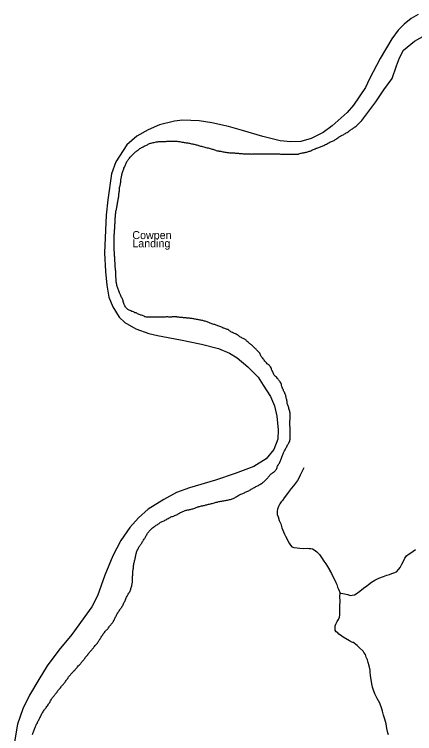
# Model space of a CAD drawing. Extents: x 1945482 to 2853149, y 66427 to 1015778.
# Drawn here: x 2303586 to 2310973, y 217061 to 230327 of the extents above; entities that cross this region are included whole.
import ezdxf

# ---------------------------------------------------------------- set-up
doc = ezdxf.new("R2010")
doc.units = 0
for name, color, linetype in [('Old_Level_21', 7, 'Continuous'), ('Old_Level_35', 7, 'Continuous'), ('Old_Level_52', 7, 'Continuous'), ('Old_Level_60', 7, 'Continuous')]:
    doc.layers.add(name, color=color, linetype=linetype)

msp = doc.modelspace()

# ---------------------------------------------------------------- linework, layer by layer
at = {"layer": 'Old_Level_35'}
for points in [[(2308930, 221960), (2308883, 221878), (2308861, 221825), (2308835, 221772), (2308809, 221729), (2308777, 221678), (2308739, 221628), (2308697, 221579), (2308640, 221510), (2308606, 221465), (2308566, 221409), (2308532, 221360), (2308511, 221335), (2308484, 221296), (2308460, 221251), (2308444, 221199), (2308439, 221164), (2308438, 221104), (2308452, 221059), (2308474, 220994), (2308501, 220929), (2308522, 220859), (2308574, 220738), (2308592, 220702), (2308655, 220571), (2308681, 220534), (2308704, 220505), (2308742, 220492), (2308804, 220485), (2308857, 220479), (2308913, 220475), (2308991, 220478), (2309025, 220475), (2309055, 220475), (2309089, 220466), (2309116, 220451), (2309171, 220415), (2309217, 220367), (2309252, 220310), (2309300, 220244), (2309334, 220193), (2309368, 220145), (2309399, 220082), (2309401, 220078), (2309437, 220016), (2309459, 219972), (2309485, 219913), (2309516, 219847), (2309535, 219811), (2309549, 219764), (2309569, 219723), (2309598, 219648)], [(2309598, 219648), (2309650, 219644), (2309741, 219627), (2309782, 219611), (2309823, 219613), (2309863, 219622), (2309895, 219638), (2309959, 219688), (2310032, 219745), (2310089, 219789), (2310122, 219813), (2310176, 219851), (2310239, 219891), (2310315, 219926), (2310396, 219960), (2310461, 219984), (2310508, 219998), (2310552, 220014), (2310605, 220032), (2310637, 220047), (2310679, 220093), (2310704, 220122), (2310739, 220189), (2310765, 220242), (2310791, 220299), (2310821, 220342), (2310852, 220366), (2310903, 220398), (2310944, 220423), (2310989, 220455)], [(2310488, 217040), (2310476, 217076), (2310459, 217155), (2310446, 217241), (2310422, 217326), (2310401, 217403), (2310382, 217476), (2310369, 217518), (2310333, 217622), (2310283, 217708), (2310238, 217797), (2310213, 217862), (2310197, 217919), (2310186, 217979), (2310160, 218130), (2310154, 218191), (2310152, 218229), (2310135, 218313), (2310115, 218370), (2310101, 218421), (2310081, 218473), (2310065, 218518), (2310037, 218557), (2310022, 218580), (2309956, 218642), (2309910, 218684), (2309830, 218745), (2309826, 218743), (2309773, 218774), (2309656, 218840), (2309605, 218874), (2309576, 218893), (2309553, 218918), (2309526, 218935), (2309507, 218968), (2309504, 219048), (2309518, 219082), (2309545, 219126), (2309569, 219164), (2309587, 219211), (2309592, 219247), (2309593, 219321), (2309593, 219412), (2309596, 219502), (2309592, 219590), (2309598, 219648)]]:
    msp.add_lwpolyline(points, dxfattribs=at)
at = {"layer": 'Old_Level_52'}
msp.add_lwpolyline([(2311041, 230327), (2310910, 230249), (2310777, 230148), (2310670, 230033), (2310554, 229875), (2310336, 229511), (2310143, 229139), (2310065, 228980), (2309845, 228651), (2309729, 228516), (2309451, 228274), (2309282, 228148), (2309061, 228036), (2308875, 227983), (2308686, 227974), (2308492, 227992), (2308171, 228072), (2307797, 228186), (2307537, 228258), (2307232, 228325), (2306995, 228361), (2306690, 228374), (2306539, 228359), (2306266, 228287), (2306053, 228199), (2305845, 228081), (2305659, 227920), (2305456, 227604), (2305381, 227384), (2305314, 226908), (2305283, 226623), (2305247, 225931), (2305247, 225931), (2305265, 225583), (2305293, 225333), (2305328, 225110), (2305406, 224932), (2305520, 224739), (2305626, 224645), (2305825, 224528), (2306065, 224443), (2306226, 224401), (2306654, 224325), (2307038, 224244), (2307353, 224161), (2307554, 224075), (2307698, 223989), (2307895, 223827), (2308085, 223633), (2308179, 223490), (2308310, 223279), (2308388, 223107), (2308432, 222916), (2308454, 222664), (2308446, 222492), (2308372, 222302), (2308230, 222131), (2308004, 221990), (2307659, 221856), (2307298, 221737), (2306817, 221594), (2306579, 221508), (2306342, 221379), (2306056, 221201), (2305876, 221040), (2305718, 220861), (2305551, 220621), (2305403, 220340), (2305258, 219982), (2305119, 219603), (2305015, 219398), (2304645, 218886), (2304404, 218602), (2304191, 218309), (2304038, 218060), (2303863, 217767), (2303743, 217519), (2303641, 217232), (2303586, 216908)], dxfattribs=at)
at = {"layer": 'Old_Level_60'}
for points in [[(2310000, 228370), (2310254, 228715), (2310403, 228933), (2310561, 229143), (2310636, 229379), (2310692, 229527), (2310766, 229667), (2310971, 229833), (2311265, 230000)], [(2308766, 227748), (2308782, 227748), (2308799, 227748), (2308815, 227749), (2308828, 227751), (2308838, 227757), (2308854, 227760), (2308871, 227764), (2308888, 227767), (2308904, 227770), (2308920, 227775), (2308935, 227778), (2308951, 227782), (2308966, 227787), (2308982, 227788), (2308997, 227794), (2309013, 227797), (2309029, 227801), (2309043, 227806), (2309060, 227812), (2309076, 227820), (2309090, 227826), (2309107, 227833), (2309125, 227841), (2309140, 227848), (2309154, 227856), (2309171, 227862), (2309187, 227867), (2309203, 227872), (2309219, 227878), (2309233, 227884), (2309248, 227890), (2309264, 227897), (2309280, 227903), (2309296, 227910), (2309313, 227918), (2309329, 227926), (2309345, 227935), (2309362, 227944), (2309378, 227952), (2309392, 227960), (2309409, 227967), (2309423, 227973), (2309438, 227979), (2309455, 227987), (2309471, 227994), (2309485, 228002), (2309498, 228011), (2309512, 228018), (2309525, 228028), (2309539, 228037), (2309555, 228049), (2309568, 228058), (2309581, 228066), (2309594, 228076), (2309609, 228086), (2309623, 228093), (2309638, 228099), (2309651, 228107), (2309665, 228112), (2309681, 228121), (2309697, 228130), (2309711, 228139), (2309727, 228148), (2309745, 228159), (2309759, 228170), (2309772, 228179), (2309785, 228189), (2309797, 228198), (2309809, 228208), (2309824, 228218), (2309837, 228226), (2309850, 228235), (2309865, 228245), (2309878, 228254), (2309892, 228265), (2309906, 228276), (2309918, 228288), (2309929, 228299), (2309940, 228310), (2309952, 228320), (2309961, 228332), (2309973, 228343), (2309985, 228355), (2309996, 228366), (2310000, 228370)], [(2305449, 226575), (2305450, 226593), (2305452, 226609), (2305454, 226627), (2305455, 226644), (2305456, 226660), (2305458, 226677), (2305460, 226695), (2305464, 226712), (2305469, 226728), (2305473, 226744), (2305476, 226759), (2305479, 226777), (2305481, 226796), (2305484, 226813), (2305487, 226830), (2305490, 226850), (2305493, 226867), (2305496, 226885), (2305499, 226900), (2305502, 226916), (2305505, 226934), (2305508, 226950), (2305511, 226965), (2305514, 226981), (2305516, 226999), (2305517, 227017), (2305519, 227034), (2305523, 227052), (2305525, 227070), (2305526, 227086), (2305527, 227102), (2305527, 227118), (2305529, 227134), (2305533, 227149), (2305536, 227164), (2305539, 227181), (2305542, 227198), (2305545, 227213), (2305548, 227229), (2305550, 227247), (2305551, 227263), (2305554, 227279), (2305556, 227294), (2305559, 227309), (2305562, 227324), (2305564, 227340), (2305567, 227355), (2305570, 227370), (2305574, 227386), (2305578, 227400), (2305583, 227415), (2305587, 227430), (2305593, 227446), (2305598, 227461), (2305604, 227476), (2305609, 227491), (2305616, 227507), (2305622, 227523), (2305628, 227536), (2305636, 227550), (2305644, 227564), (2305651, 227581), (2305657, 227596), (2305664, 227612), (2305671, 227625), (2305682, 227639), (2305691, 227652), (2305701, 227663), (2305711, 227677), (2305722, 227690), (2305735, 227704), (2305747, 227717), (2305759, 227728), (2305772, 227742), (2305784, 227755), (2305796, 227766), (2305810, 227778), (2305822, 227789), (2305834, 227800), (2305849, 227812), (2305863, 227822), (2305877, 227831), (2305889, 227841), (2305904, 227850), (2305922, 227862), (2305935, 227870), (2305948, 227878), (2305961, 227885), (2305979, 227893), (2305995, 227900), (2306011, 227908), (2306027, 227915), (2306042, 227921), (2306055, 227930), (2306069, 227938), (2306082, 227946), (2306097, 227950), (2306112, 227954)], [(2306112, 227954), (2306130, 227958), (2306147, 227962), (2306165, 227966), (2306184, 227970), (2306200, 227973), (2306214, 227976), (2306232, 227978), (2306247, 227980), (2306263, 227981), (2306278, 227982), (2306297, 227983), (2306316, 227984), (2306334, 227984), (2306351, 227985), (2306367, 227985), (2306385, 227985), (2306401, 227986), (2306417, 227987), (2306436, 227989), (2306455, 227989), (2306471, 227989), (2306488, 227990), (2306507, 227990), (2306526, 227990), (2306544, 227989), (2306562, 227988), (2306577, 227987), (2306593, 227986), (2306610, 227983), (2306626, 227979), (2306641, 227979), (2306657, 227974), (2306674, 227971), (2306690, 227970), (2306706, 227967), (2306722, 227965), (2306738, 227962), (2306755, 227959), (2306770, 227957), (2306788, 227955), (2306805, 227953), (2306821, 227949), (2306837, 227944), (2306854, 227941), (2306873, 227938), (2306891, 227935), (2306906, 227931), (2306921, 227927), (2306939, 227922), (2306955, 227918), (2306971, 227914), (2306987, 227909), (2307002, 227904), (2307022, 227898), (2307040, 227893), (2307059, 227888), (2307080, 227883), (2307101, 227878), (2307122, 227873), (2307142, 227868), (2307161, 227863), (2307180, 227859), (2307199, 227854), (2307217, 227848), (2307234, 227843), (2307249, 227839), (2307266, 227834), (2307282, 227828), (2307298, 227822), (2307313, 227815), (2307328, 227812), (2307344, 227810), (2307358, 227808), (2307367, 227803), (2307383, 227802), (2307399, 227801), (2307415, 227796), (2307433, 227793), (2307451, 227790), (2307469, 227786), (2307488, 227783), (2307505, 227781), (2307523, 227779), (2307540, 227777), (2307555, 227776), (2307571, 227775), (2307586, 227776), (2307602, 227776), (2307617, 227774), (2307633, 227773), (2307651, 227771), (2307669, 227769), (2307687, 227767), (2307706, 227766), (2307721, 227765), (2307736, 227763), (2307752, 227762), (2307770, 227760)], [(2307770, 227760), (2307790, 227758), (2307808, 227757), (2307828, 227756), (2307844, 227755), (2307859, 227755), (2307878, 227755), (2307895, 227754), (2307911, 227753), (2307930, 227752), (2307949, 227752), (2307964, 227751), (2307981, 227752), (2308000, 227752), (2308015, 227753), (2308039, 227753), (2308054, 227753), (2308073, 227754), (2308092, 227754), (2308108, 227753), (2308125, 227753), (2308140, 227753), (2308162, 227753), (2308183, 227753), (2308203, 227753), (2308222, 227753), (2308241, 227752), (2308260, 227752), (2308278, 227752), (2308297, 227753), (2308317, 227753), (2308341, 227754), (2308356, 227754), (2308375, 227754), (2308395, 227754), (2308411, 227754), (2308429, 227754), (2308444, 227753), (2308463, 227753), (2308482, 227752), (2308499, 227751), (2308515, 227751), (2308533, 227751), (2308548, 227751), (2308564, 227751), (2308580, 227749), (2308595, 227749), (2308611, 227749), (2308628, 227749), (2308645, 227749), (2308663, 227749), (2308683, 227747), (2308700, 227746), (2308717, 227747), (2308733, 227747), (2308748, 227747), (2308766, 227748)], [(2305449, 225659), (2305448, 225677), (2305447, 225696), (2305446, 225713), (2305445, 225729), (2305444, 225749), (2305443, 225764), (2305443, 225781), (2305442, 225797), (2305441, 225816), (2305439, 225834), (2305438, 225850), (2305437, 225867), (2305437, 225882), (2305437, 225898), (2305436, 225915), (2305435, 225930), (2305432, 225945), (2305429, 225962), (2305428, 225977), (2305428, 225994), (2305428, 226010), (2305427, 226028), (2305427, 226044), (2305427, 226060), (2305430, 226077), (2305431, 226092), (2305431, 226108), (2305430, 226123), (2305430, 226139), (2305430, 226155), (2305429, 226171), (2305430, 226187), (2305430, 226203), (2305430, 226219), (2305429, 226235), (2305430, 226251), (2305431, 226267), (2305432, 226283), (2305432, 226301), (2305433, 226318), (2305435, 226337), (2305437, 226354), (2305439, 226372), (2305440, 226391), (2305441, 226407), (2305441, 226424), (2305442, 226439), (2305443, 226456), (2305445, 226474), (2305446, 226492), (2305446, 226509), (2305447, 226525), (2305447, 226542), (2305448, 226560), (2305449, 226575)], [(2306455, 224744), (2306437, 224744), (2306421, 224745), (2306404, 224745), (2306387, 224745), (2306368, 224744), (2306352, 224744), (2306334, 224743), (2306317, 224743), (2306301, 224743), (2306286, 224744), (2306270, 224744), (2306254, 224744), (2306236, 224744), (2306220, 224743), (2306205, 224743), (2306190, 224743), (2306173, 224742), (2306158, 224742), (2306142, 224742), (2306126, 224741), (2306107, 224741), (2306089, 224741), (2306073, 224740), (2306055, 224742), (2306040, 224743), (2306023, 224744), (2306008, 224745), (2305993, 224750), (2305979, 224758), (2305964, 224766), (2305950, 224771), (2305934, 224776), (2305920, 224781), (2305905, 224786), (2305891, 224793), (2305876, 224799), (2305861, 224806), (2305847, 224813), (2305832, 224819), (2305824, 224822), (2305812, 224824), (2305798, 224832), (2305784, 224839), (2305769, 224844), (2305753, 224849), (2305738, 224858), (2305724, 224863), (2305707, 224871), (2305693, 224877), (2305679, 224885), (2305667, 224896), (2305656, 224907), (2305644, 224920), (2305636, 224935), (2305627, 224948), (2305618, 224963), (2305612, 224978), (2305607, 224994), (2305602, 225012), (2305597, 225028), (2305591, 225043), (2305586, 225059), (2305579, 225076), (2305573, 225090), (2305565, 225105), (2305559, 225120), (2305553, 225135), (2305546, 225151), (2305538, 225164), (2305530, 225178), (2305524, 225193), (2305518, 225209), (2305511, 225228), (2305505, 225243), (2305499, 225260), (2305495, 225276), (2305490, 225294), (2305485, 225309), (2305479, 225328), (2305475, 225344), (2305471, 225361), (2305469, 225377), (2305467, 225392), (2305466, 225408), (2305465, 225426), (2305463, 225443), (2305462, 225459), (2305461, 225476), (2305460, 225496), (2305459, 225513), (2305459, 225533), (2305458, 225552), (2305457, 225571), (2305456, 225592), (2305454, 225608), (2305453, 225627), (2305451, 225643), (2305449, 225659)], [(2307924, 224258), (2307911, 224269), (2307898, 224281), (2307885, 224292), (2307872, 224303), (2307861, 224316), (2307850, 224326), (2307837, 224335), (2307823, 224340), (2307809, 224349), (2307793, 224357), (2307778, 224365), (2307762, 224373), (2307749, 224381), (2307736, 224391), (2307723, 224401), (2307710, 224411), (2307695, 224419), (2307681, 224426), (2307665, 224434), (2307648, 224443), (2307631, 224449), (2307613, 224456), (2307596, 224464), (2307581, 224473), (2307567, 224481), (2307555, 224492), (2307542, 224503), (2307530, 224512), (2307515, 224517), (2307499, 224520), (2307484, 224525), (2307469, 224530), (2307454, 224536), (2307440, 224542), (2307426, 224549), (2307409, 224556), (2307394, 224564), (2307377, 224571), (2307361, 224577), (2307344, 224583), (2307329, 224588), (2307313, 224593), (2307298, 224599), (2307283, 224604), (2307268, 224608), (2307250, 224613), (2307233, 224619), (2307218, 224625), (2307202, 224632), (2307188, 224637), (2307173, 224644), (2307158, 224649), (2307143, 224653), (2307126, 224659), (2307108, 224666), (2307094, 224671), (2307079, 224675), (2307063, 224678), (2307048, 224682), (2307030, 224684), (2307015, 224688), (2306999, 224692), (2306985, 224695), (2306965, 224698), (2306949, 224700), (2306931, 224705), (2306915, 224707), (2306900, 224711), (2306885, 224714), (2306868, 224715), (2306852, 224718), (2306836, 224720), (2306819, 224721), (2306801, 224721), (2306785, 224723), (2306770, 224725), (2306755, 224729), (2306739, 224732), (2306724, 224732), (2306707, 224732), (2306691, 224734), (2306676, 224736), (2306659, 224737), (2306642, 224737), (2306624, 224740), (2306608, 224741), (2306592, 224743), (2306582, 224744), (2306583, 224745), (2306567, 224746), (2306551, 224746), (2306535, 224745), (2306517, 224745), (2306501, 224745), (2306486, 224744), (2306471, 224744), (2306455, 224744)], [(2308480, 223559), (2308472, 223572), (2308463, 223586), (2308452, 223600), (2308443, 223612), (2308431, 223626), (2308421, 223638), (2308407, 223649), (2308392, 223659), (2308380, 223669), (2308373, 223685), (2308367, 223702), (2308360, 223718), (2308354, 223733), (2308348, 223747), (2308340, 223762), (2308333, 223779), (2308329, 223794), (2308323, 223808), (2308313, 223823), (2308303, 223837), (2308292, 223850), (2308279, 223864), (2308266, 223875), (2308252, 223884), (2308241, 223897), (2308231, 223908), (2308219, 223919), (2308208, 223933), (2308197, 223946), (2308189, 223961), (2308177, 223976), (2308165, 223990), (2308153, 224001), (2308141, 224014), (2308134, 224028), (2308128, 224044), (2308121, 224060), (2308114, 224076), (2308104, 224089), (2308091, 224102), (2308078, 224114), (2308067, 224125), (2308057, 224138), (2308047, 224150), (2308034, 224160), (2308022, 224172), (2308011, 224184), (2307999, 224196), (2307987, 224207), (2307975, 224218), (2307962, 224229), (2307949, 224238), (2307936, 224248), (2307924, 224258)], [(2308445, 221996), (2308454, 222010), (2308462, 222023), (2308469, 222036), (2308477, 222050), (2308485, 222065), (2308491, 222080), (2308497, 222096), (2308503, 222112), (2308510, 222127), (2308517, 222144), (2308522, 222158), (2308528, 222175), (2308533, 222191), (2308539, 222207), (2308545, 222223), (2308550, 222238), (2308557, 222252), (2308565, 222265), (2308573, 222279), (2308581, 222293), (2308589, 222309), (2308597, 222324), (2308605, 222339), (2308614, 222353), (2308622, 222368), (2308629, 222384), (2308637, 222399), (2308644, 222413), (2308654, 222427), (2308661, 222441), (2308668, 222458), (2308672, 222474), (2308675, 222490), (2308678, 222505), (2308678, 222521), (2308678, 222538), (2308677, 222553), (2308677, 222569), (2308677, 222585), (2308676, 222601), (2308676, 222618), (2308676, 222635), (2308675, 222652), (2308675, 222668), (2308674, 222684), (2308674, 222702), (2308673, 222718), (2308672, 222734), (2308672, 222750), (2308672, 222766), (2308671, 222783), (2308671, 222800), (2308671, 222817), (2308672, 222833), (2308675, 222851), (2308677, 222867), (2308677, 222883), (2308677, 222902), (2308676, 222917), (2308676, 222934), (2308675, 222952), (2308673, 222970), (2308670, 222987), (2308667, 223004), (2308664, 223021), (2308658, 223039), (2308653, 223055), (2308649, 223072), (2308644, 223088), (2308638, 223105), (2308632, 223120), (2308627, 223137), (2308623, 223152), (2308620, 223170), (2308618, 223186), (2308615, 223202), (2308613, 223218), (2308609, 223233), (2308605, 223248), (2308601, 223264), (2308597, 223280), (2308593, 223295), (2308588, 223310), (2308583, 223324), (2308576, 223341), (2308569, 223357), (2308562, 223372), (2308556, 223386), (2308550, 223400), (2308543, 223416), (2308536, 223432), (2308530, 223448), (2308524, 223466), (2308519, 223485), (2308515, 223500), (2308509, 223518), (2308501, 223533), (2308490, 223547), (2308480, 223559)], [(2308403, 221913), (2308414, 221925), (2308422, 221938), (2308428, 221952), (2308433, 221968), (2308439, 221982), (2308445, 221996)], [(2306914, 221221), (2306930, 221227), (2306944, 221233), (2306958, 221238), (2306973, 221243), (2306982, 221245), (2306991, 221248), (2307005, 221251), (2307022, 221255), (2307039, 221259), (2307056, 221263), (2307072, 221268), (2307087, 221271), (2307106, 221276), (2307121, 221279), (2307136, 221283), (2307150, 221287), (2307169, 221291), (2307188, 221294), (2307206, 221298), (2307222, 221302), (2307239, 221306), (2307258, 221311), (2307277, 221316), (2307294, 221322), (2307310, 221327), (2307326, 221331), (2307344, 221336), (2307360, 221340), (2307378, 221343), (2307396, 221347), (2307415, 221350), (2307433, 221354), (2307451, 221356), (2307468, 221359), (2307485, 221362), (2307500, 221365), (2307518, 221369), (2307537, 221372), (2307555, 221376), (2307573, 221379), (2307591, 221384), (2307606, 221390), (2307622, 221397), (2307637, 221404), (2307652, 221410), (2307668, 221419), (2307682, 221427), (2307697, 221438), (2307710, 221447), (2307726, 221456), (2307739, 221464), (2307753, 221470), (2307768, 221476), (2307785, 221482), (2307800, 221489), (2307815, 221495), (2307832, 221504), (2307846, 221512), (2307862, 221519), (2307879, 221525), (2307896, 221532), (2307912, 221540), (2307928, 221548), (2307941, 221557), (2307956, 221567), (2307971, 221576), (2307986, 221584), (2308000, 221591), (2308016, 221600), (2308029, 221608), (2308044, 221616), (2308059, 221624), (2308074, 221632), (2308089, 221640), (2308106, 221649), (2308119, 221657), (2308133, 221666), (2308148, 221675), (2308163, 221685), (2308178, 221696), (2308192, 221706), (2308203, 221716), (2308216, 221728), (2308228, 221739), (2308240, 221752), (2308251, 221764), (2308261, 221778), (2308271, 221791), (2308281, 221802), (2308292, 221816), (2308303, 221828), (2308313, 221841), (2308326, 221852), (2308339, 221861), (2308353, 221870), (2308367, 221881), (2308380, 221892), (2308392, 221902), (2308403, 221913)], [(2305786, 220161), (2305789, 220178), (2305793, 220197), (2305798, 220215), (2305801, 220230), (2305805, 220247), (2305810, 220263), (2305814, 220281), (2305818, 220298), (2305821, 220313), (2305823, 220329), (2305826, 220346), (2305829, 220363), (2305834, 220379), (2305838, 220396), (2305843, 220410), (2305848, 220426), (2305855, 220441), (2305862, 220455), (2305868, 220469), (2305875, 220483), (2305883, 220497), (2305891, 220511), (2305901, 220523), (2305909, 220537), (2305919, 220549), (2305929, 220560), (2305938, 220575), (2305945, 220590), (2305953, 220604), (2305962, 220618), (2305970, 220631), (2305980, 220646), (2305989, 220659), (2305997, 220673), (2306005, 220686), (2306013, 220700), (2306020, 220713), (2306028, 220727), (2306036, 220743), (2306044, 220756), (2306054, 220770), (2306065, 220781), (2306075, 220794), (2306085, 220807), (2306098, 220820), (2306111, 220833), (2306123, 220845), (2306136, 220856), (2306151, 220868), (2306164, 220876), (2306177, 220884), (2306190, 220893), (2306205, 220903), (2306219, 220911), (2306234, 220921), (2306246, 220930), (2306260, 220939), (2306273, 220949), (2306285, 220958), (2306299, 220966), (2306315, 220973), (2306331, 220979), (2306348, 220987), (2306366, 220997), (2306384, 221006), (2306397, 221013), (2306409, 221021), (2306426, 221031), (2306442, 221040), (2306459, 221048), (2306475, 221056), (2306492, 221063), (2306507, 221068), (2306526, 221074), (2306543, 221081), (2306561, 221088), (2306578, 221096), (2306594, 221104), (2306608, 221112), (2306623, 221120), (2306639, 221130), (2306653, 221139), (2306668, 221146), (2306684, 221153), (2306698, 221158), (2306712, 221164), (2306726, 221171), (2306740, 221175), (2306755, 221179), (2306770, 221185), (2306787, 221189), (2306804, 221191), (2306819, 221193), (2306836, 221196), (2306851, 221200), (2306867, 221204), (2306882, 221208), (2306897, 221214), (2306914, 221221)], [(2305120, 218729), (2305129, 218745), (2305136, 218758), (2305145, 218772), (2305154, 218785), (2305161, 218798), (2305172, 218814), (2305181, 218828), (2305190, 218842), (2305200, 218855), (2305209, 218868), (2305218, 218883), (2305228, 218899), (2305239, 218914), (2305251, 218927), (2305262, 218941), (2305271, 218954), (2305282, 218966), (2305293, 218977), (2305303, 218988), (2305315, 219001), (2305324, 219014), (2305333, 219029), (2305342, 219043), (2305352, 219055), (2305364, 219068), (2305375, 219081), (2305385, 219092), (2305395, 219105), (2305405, 219116), (2305414, 219129), (2305418, 219143), (2305427, 219156), (2305435, 219169), (2305441, 219183), (2305447, 219199), (2305455, 219215), (2305464, 219229), (2305471, 219243), (2305478, 219256), (2305486, 219270), (2305494, 219286), (2305503, 219301), (2305511, 219315), (2305520, 219328), (2305531, 219341), (2305541, 219353), (2305550, 219366), (2305560, 219380), (2305568, 219394), (2305577, 219409), (2305586, 219422), (2305593, 219437), (2305600, 219452), (2305608, 219470), (2305615, 219486), (2305622, 219499), (2305631, 219514), (2305638, 219528), (2305644, 219544), (2305651, 219562), (2305658, 219577), (2305665, 219594), (2305671, 219609), (2305678, 219622), (2305687, 219635), (2305697, 219649), (2305706, 219663), (2305714, 219677), (2305722, 219692), (2305728, 219708), (2305733, 219723), (2305738, 219739), (2305742, 219754), (2305747, 219770), (2305751, 219786), (2305755, 219802), (2305759, 219818), (2305761, 219833), (2305764, 219848), (2305765, 219865), (2305766, 219880), (2305768, 219898), (2305768, 219913), (2305769, 219929), (2305769, 219946), (2305769, 219964), (2305771, 219980), (2305772, 219995), (2305772, 220000), (2305773, 220013), (2305773, 220029), (2305773, 220047), (2305775, 220062), (2305777, 220077), (2305780, 220095), (2305782, 220111), (2305784, 220126), (2305784, 220141), (2305786, 220161)], [(2304087, 217413), (2304096, 217430), (2304105, 217445), (2304115, 217461), (2304124, 217476), (2304134, 217492), (2304143, 217505), (2304153, 217517), (2304164, 217530), (2304176, 217545), (2304188, 217559), (2304198, 217575), (2304208, 217592), (2304218, 217607), (2304229, 217622), (2304241, 217637), (2304249, 217651), (2304256, 217667), (2304266, 217685), (2304274, 217699), (2304283, 217712), (2304292, 217725), (2304302, 217738), (2304312, 217752), (2304323, 217765), (2304332, 217777), (2304342, 217788), (2304354, 217801), (2304364, 217814), (2304373, 217828), (2304382, 217843), (2304392, 217857), (2304402, 217870), (2304412, 217881), (2304426, 217895), (2304438, 217908), (2304450, 217922), (2304459, 217935), (2304470, 217948), (2304480, 217960), (2304491, 217971), (2304502, 217984), (2304512, 217997), (2304522, 218012), (2304531, 218024), (2304540, 218038), (2304550, 218052), (2304560, 218066), (2304570, 218080), (2304579, 218093), (2304588, 218105), (2304599, 218118), (2304609, 218130), (2304620, 218145), (2304631, 218158), (2304643, 218171), (2304653, 218182), (2304663, 218195), (2304673, 218207), (2304686, 218219), (2304699, 218233), (2304709, 218244), (2304721, 218256), (2304732, 218268), (2304744, 218281), (2304753, 218293), (2304766, 218308), (2304780, 218322), (2304793, 218336), (2304804, 218347), (2304815, 218361), (2304824, 218374), (2304834, 218385), (2304845, 218396), (2304856, 218407), (2304866, 218419), (2304875, 218434), (2304884, 218448), (2304894, 218463), (2304905, 218477), (2304916, 218489), (2304927, 218503), (2304939, 218516), (2304950, 218530), (2304961, 218545), (2304971, 218557), (2304980, 218569), (2304992, 218583), (2305003, 218594), (2305014, 218606), (2305025, 218619), (2305035, 218631), (2305045, 218643), (2305055, 218657), (2305065, 218670), (2305075, 218683), (2305086, 218694), (2305098, 218704), (2305110, 218717), (2305120, 218729)], [(2303920, 217046), (2303926, 217062), (2303932, 217078), (2303938, 217095), (2303943, 217111), (2303949, 217126), (2303956, 217142), (2303963, 217159), (2303970, 217175), (2303977, 217189), (2303983, 217204), (2303989, 217219), (2303996, 217232), (2304004, 217249), (2304011, 217264), (2304018, 217281), (2304026, 217297), (2304035, 217311), (2304043, 217324), (2304051, 217341), (2304059, 217354), (2304067, 217370), (2304073, 217385), (2304080, 217399), (2304087, 217413)]]:
    msp.add_lwpolyline(points, dxfattribs=at)

# ---------------------------------------------------------------- texts
at = {"layer": 'Old_Level_21'}
for s, p in [('Cowpen', (2305763, 226182)), ('Landing', (2305763, 226030))]:
    msp.add_text(s, height=147.6, dxfattribs=at).set_placement(p)

doc.saveas('drawing.dxf')
